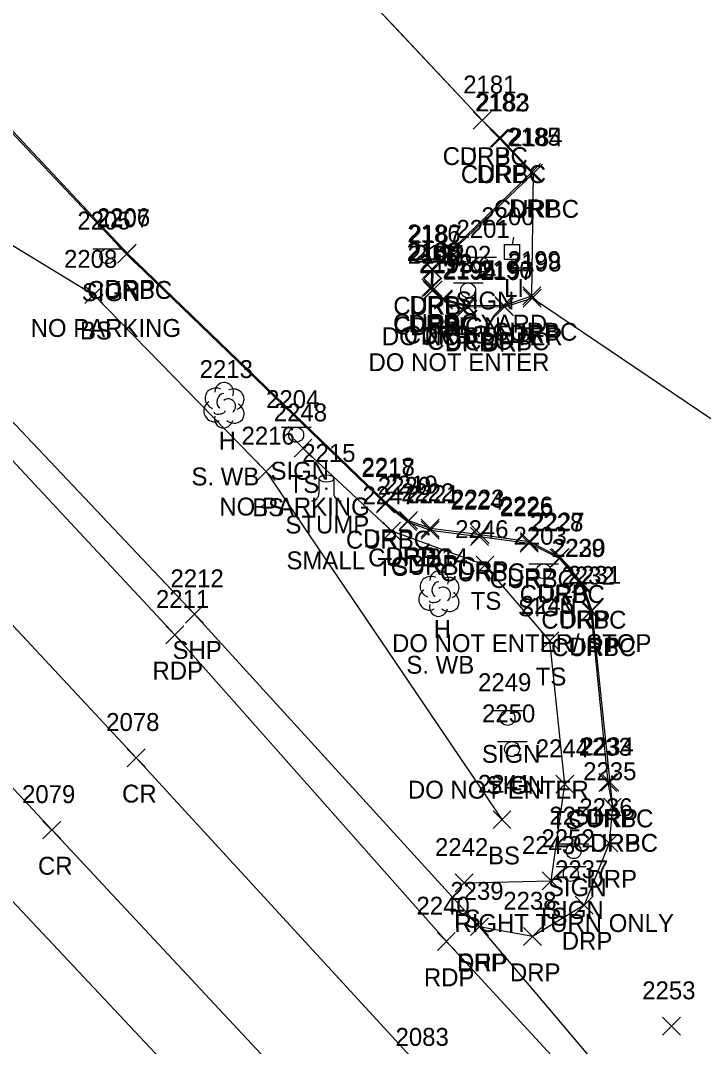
# Model space of a CAD drawing. Extents: x 1623612 to 1625808, y 621345 to 627748.
# Drawn here: x 1624292.6 to 1624368.9, y 626796.7 to 626911.4 of the extents above; entities that cross this region are included whole.
import ezdxf

# ---------------------------------------------------------------- set-up
doc = ezdxf.new("R2010")
doc.units = 0
for name, color, linetype in [('L_A', 7, 'Continuous'), ('L_C', 7, 'Continuous'), ('L_I', 7, 'Continuous'), ('L_TIC', 7, 'Continuous'), ('LELB', 7, 'Continuous'), ('LSOGP', 7, 'Continuous'), ('LTD', 7, 'Continuous'), ('LTS', 7, 'Continuous'), ('P_A', 7, 'Continuous'), ('P_I', 7, 'Continuous'), ('P_TIC', 7, 'Continuous'), ('PET', 7, 'Continuous'), ('PRC', 7, 'Continuous'), ('PSP', 7, 'Continuous'), ('R_A', 7, 'Continuous'), ('R_I', 7, 'Continuous'), ('R_TIC', 7, 'Continuous'), ('RC', 7, 'Continuous'), ('RDP', 7, 'Continuous'), ('S_A', 7, 'Continuous'), ('S_C', 7, 'Continuous'), ('S_I', 7, 'Continuous'), ('SSGN', 7, 'Continuous'), ('U_A', 7, 'Continuous'), ('U_C', 7, 'Continuous'), ('U_I', 7, 'Continuous'), ('ULP', 7, 'Continuous')]:
    doc.layers.add(name, color=color, linetype=linetype)

msp = doc.modelspace()

# ---------------------------------------------------------------- linework, layer by layer
at = {"layer": 'L_TIC'}
for points in [[(1624299.83, 626879.73), (1624301.83, 626881.73)], [(1624301.83, 626879.73), (1624299.83, 626881.73)], [(1624323.18, 626862.58), (1624325.18, 626864.58)], [(1624325.18, 626862.58), (1624323.18, 626864.58)], [(1624319.07, 626859.98), (1624321.07, 626861.98)], [(1624321.07, 626859.98), (1624319.07, 626861.98)], [(1624333.09, 626853.32), (1624335.09, 626855.32)], [(1624335.09, 626853.32), (1624333.09, 626855.32)], [(1624343.51, 626849.53), (1624345.51, 626851.53)], [(1624345.51, 626849.53), (1624343.51, 626851.53)], [(1624350.77, 626841.07), (1624352.77, 626843.07)], [(1624352.77, 626841.07), (1624350.77, 626843.07)], [(1624352.44, 626825.05), (1624354.44, 626827.05)], [(1624354.44, 626825.05), (1624352.44, 626827.05)], [(1624345.41, 626821.08), (1624347.41, 626823.08)], [(1624347.41, 626821.08), (1624345.41, 626823.08)], [(1624350.9, 626814.24), (1624352.9, 626816.24)], [(1624352.9, 626814.24), (1624350.9, 626816.24)], [(1624341.19, 626814.02), (1624343.19, 626816.02)], [(1624343.19, 626814.02), (1624341.19, 626816.02)], [(1624364.34, 626798.01), (1624366.34, 626800.01)], [(1624366.34, 626798.01), (1624364.34, 626800.01)]]:
    msp.add_lwpolyline(points, dxfattribs=at)
at = {"layer": 'LELB'}
for points in [[(1624269.61, 626899.7), (1624300.83, 626880.73), (1624320.07, 626860.98), (1624346.41, 626822.08)], [(1624342.19, 626815.02), (1624351.9, 626815.24), (1624353.44, 626826.05), (1624351.77, 626842.07), (1624344.51, 626850.53), (1624334.09, 626854.32), (1624324.18, 626863.58)]]:
    msp.add_lwpolyline(points, dxfattribs=at)
at = {"layer": 'LSOGP'}
msp.add_lwpolyline([(1624379.94, 626859.96), (1624349.79, 626880.33), (1624349.74, 626880.59), (1624349.93, 626894.32), (1624346.24, 626898.2), (1624344.21, 626900.21), (1624339.12, 626905.63), (1624334.03, 626911.05), (1624328.94, 626916.48)], dxfattribs=at)
at = {"layer": 'LTD'}
for p, q in [((1624315.33, 626868.42), (1624315.33, 626868.42)), ((1624315.33, 626868.42), (1624315.33, 626868.42)), ((1624339.34, 626847.38), (1624339.34, 626847.38)), ((1624339.34, 626847.38), (1624339.34, 626847.38))]:
    msp.add_line(p, q, dxfattribs=at)
for centre in [(1624315.38, 626869.86), (1624339.39, 626848.82)]:
    msp.add_arc(centre, 1.05, 335.5272, 180.9563, dxfattribs=at)
for centre, major_axis, ratio, start_param, end_param in [((1624314.54, 626869.09), (1.21, -0.51), 0.895232, 1.570796, 4.712389), ((1624316.37, 626869.01), (-1.14, -0.48), 0.949671, 1.570796, 4.712389), ((1624315.12, 626868.88), (-0.208, -0.792), 0.645439, 3.141593, 6.283185), ((1624315.83, 626868.26), (-0.5, 0.667), 0.989748, 3.141593, 6.283185), ((1624314.25, 626867.71), (0.58, -1.04), 0.959034, 3.141593, 6.283185), ((1624316.33, 626867.59), (-1.09, 0.79), 0.841452, 1.570796, 4.712389), ((1624315.33, 626866.92), (0.26, 1.06), 0.942809, 1.570796, 4.712389), ((1624314.87, 626867.67), (-0.625, -0.083), 0.423636, 0, 3.141593), ((1624338.55, 626848.05), (1.21, -0.51), 0.895232, 1.570796, 4.712389), ((1624339.14, 626847.84), (-0.208, -0.792), 0.645439, 3.141593, 6.283185), ((1624340.39, 626847.97), (-1.14, -0.48), 0.949671, 1.570796, 4.712389), ((1624338.26, 626846.67), (0.58, -1.04), 0.959034, 3.141593, 6.283185), ((1624339.84, 626847.22), (-0.5, 0.667), 0.989748, 3.141593, 6.283185), ((1624340.34, 626846.55), (-1.09, 0.79), 0.841452, 1.570796, 4.712389), ((1624339.34, 626845.88), (0.26, 1.06), 0.942809, 1.570796, 4.712389), ((1624338.89, 626846.63), (-0.625, -0.083), 0.423636, 0, 3.141593)]:
    msp.add_ellipse(centre, major_axis=major_axis, ratio=ratio, start_param=start_param, end_param=end_param, dxfattribs=at)
at = {"layer": 'LTS'}
for p, q in [((1624325.96, 626860.19), (1624325.96, 626858.52)), ((1624327.63, 626860.02), (1624327.63, 626860.19)), ((1624327.63, 626860.19), (1624327.63, 626858.52)), ((1624326.8, 626859.05), (1624326.8, 626859.05)), ((1624326.8, 626859.05), (1624326.8, 626859.05)), ((1624326.8, 626859.02), (1624326.8, 626859.02))]:
    msp.add_line(p, q, dxfattribs=at)
msp.add_circle((1624326.8, 626859.05), 0.0833, dxfattribs=at)
for centre, start, end in [((1624325.13, 626858.52), 270, 360), ((1624328.46, 626858.52), 180, 270)]:
    msp.add_arc(centre, 0.833, start, end, dxfattribs=at)
msp.add_ellipse((1624326.8, 626860.19), major_axis=(-0.833, 0), ratio=0.5, dxfattribs=at)
at = {"layer": 'P_TIC'}
for points in [[(1624311.07, 626844.04), (1624313.07, 626846.04)], [(1624313.07, 626844.04), (1624311.07, 626846.04)], [(1624308.88, 626841.73), (1624310.88, 626843.73)], [(1624310.88, 626841.73), (1624308.88, 626843.73)], [(1624304.54, 626827.99), (1624306.54, 626829.99)], [(1624306.54, 626827.99), (1624304.54, 626829.99)], [(1624295.14, 626819.93), (1624297.14, 626821.93)], [(1624297.14, 626819.93), (1624295.14, 626821.93)], [(1624342.91, 626809.12), (1624344.91, 626811.12)], [(1624344.91, 626809.12), (1624342.91, 626811.12)], [(1624339.2, 626807.47), (1624341.2, 626809.47)], [(1624341.2, 626807.47), (1624339.2, 626809.47)]]:
    msp.add_lwpolyline(points, dxfattribs=at)
at = {"layer": 'PET'}
msp.add_lwpolyline([(1624211.36, 626948.94), (1624238.72, 626919.55), (1624262.36, 626893.71), (1624286.05, 626868.28), (1624309.88, 626842.73), (1624340.2, 626808.47), (1624365.34, 626781.16), (1624395.18, 626750.47), (1624419.59, 626724.64), (1624445.91, 626697.02), (1624473.1, 626668.14), (1624507.26, 626632.06), (1624527.99, 626609.86), (1624550.6, 626585.36), (1624578.26, 626556.05), (1624603.3, 626530.62), (1624620.59, 626513.39), (1624649.07, 626495.66), (1624671.18, 626489.46), (1624702.74, 626490.16)], dxfattribs=at)
at = {"layer": 'PRC'}
for points in [[(1624202.38, 626941), (1624231.95, 626909.33), (1624268.3, 626868.91), (1624305.54, 626828.99), (1624337.86, 626793.81), (1624369.19, 626760.84), (1624403.29, 626724.16), (1624436.76, 626689.12), (1624471.08, 626653.03), (1624500.99, 626619.01), (1624533.46, 626585.06), (1624572.18, 626543.82), (1624598.35, 626515.6), (1624627.03, 626484.27), (1624657.97, 626450.75), (1624685.1, 626421.27), (1624710.89, 626393.93)], [(1624192.12, 626932.46), (1624222.52, 626900.06), (1624257.95, 626861.76), (1624296.14, 626820.93), (1624328.33, 626786.43), (1624360.02, 626752.63), (1624393.53, 626716.71), (1624427.43, 626680.74), (1624459.98, 626645.81), (1624494.27, 626609.22)], [(1624186.13, 626926.24), (1624216.09, 626894.04), (1624252.24, 626855.54), (1624289.91, 626814.88), (1624322.01, 626780.73), (1624353.66, 626746.64), (1624386.67, 626711.08), (1624421.34, 626674.27), (1624454.07, 626638.87), (1624487.99, 626602.6), (1624516.65, 626571.23)]]:
    msp.add_lwpolyline(points, dxfattribs=at)
at = {"layer": 'PSP'}
msp.add_lwpolyline([(1624213.53, 626951.11), (1624241.13, 626921.37), (1624264.77, 626895.8), (1624288.11, 626870.32), (1624312.07, 626845.04), (1624343.91, 626810.12), (1624367.27, 626782.46), (1624384.8, 626765.81), (1624396.96, 626752.53), (1624422.27, 626726.83), (1624449.32, 626699.43), (1624476.73, 626671.47), (1624511.72, 626635.98), (1624532.99, 626613.93), (1624555.81, 626591.77), (1624557.1, 626590.85), (1624584.71, 626562.13), (1624609.17, 626536.98), (1624624.05, 626517.59), (1624651.19, 626501.54), (1624672.81, 626495.1), (1624698.38, 626495.38)], dxfattribs=at)
at = {"layer": 'R_TIC'}
for points in [[(1624343.21, 626899.21), (1624345.21, 626901.21)], [(1624345.21, 626899.21), (1624343.21, 626901.21)], [(1624343.21, 626899.21), (1624345.21, 626901.21)], [(1624345.21, 626899.21), (1624343.21, 626901.21)], [(1624345.1, 626897.22), (1624347.1, 626899.22)], [(1624347.1, 626897.22), (1624345.1, 626899.22)], [(1624345.24, 626897.2), (1624347.24, 626899.2)], [(1624347.24, 626897.2), (1624345.24, 626899.2)], [(1624348.7, 626893.38), (1624350.7, 626895.38)], [(1624350.7, 626893.38), (1624348.7, 626895.38)], [(1624348.93, 626893.32), (1624350.93, 626895.32)], [(1624350.93, 626893.32), (1624348.93, 626895.32)], [(1624303.48, 626884.26), (1624305.48, 626886.26)], [(1624305.48, 626884.26), (1624303.48, 626886.26)], [(1624303.56, 626884.38), (1624305.56, 626886.38)], [(1624305.56, 626884.38), (1624303.56, 626886.38)], [(1624337.59, 626882.57), (1624339.59, 626884.57)], [(1624339.59, 626882.57), (1624337.59, 626884.57)], [(1624337.68, 626882.49), (1624339.68, 626884.49)], [(1624339.68, 626882.49), (1624337.68, 626884.49)], [(1624337.46, 626880.51), (1624339.46, 626882.51)], [(1624339.46, 626880.51), (1624337.46, 626882.51)], [(1624337.66, 626880.58), (1624339.66, 626882.58)], [(1624339.66, 626880.58), (1624337.66, 626882.58)], [(1624337.66, 626880.19), (1624339.66, 626882.19)], [(1624339.66, 626880.19), (1624337.66, 626882.19)], [(1624337.73, 626880.29), (1624339.73, 626882.29)], [(1624339.73, 626880.29), (1624337.73, 626882.29)], [(1624348.74, 626879.59), (1624350.74, 626881.59)], [(1624350.74, 626879.59), (1624348.74, 626881.59)], [(1624338.86, 626879.27), (1624340.86, 626881.27)], [(1624340.86, 626879.27), (1624338.86, 626881.27)], [(1624338.87, 626879.13), (1624340.87, 626881.13)], [(1624340.87, 626879.13), (1624338.87, 626881.13)], [(1624341.45, 626878.57), (1624343.45, 626880.57)], [(1624343.45, 626878.57), (1624341.45, 626880.57)], [(1624345.6, 626878.52), (1624347.6, 626880.52)], [(1624347.6, 626878.52), (1624345.6, 626880.52)], [(1624348.79, 626879.33), (1624350.79, 626881.33)], [(1624350.79, 626879.33), (1624348.79, 626881.33)], [(1624341.53, 626878.4), (1624343.53, 626880.4)], [(1624343.53, 626878.4), (1624341.53, 626880.4)], [(1624345.68, 626878.37), (1624347.68, 626880.37)], [(1624347.68, 626878.37), (1624345.68, 626880.37)], [(1624332.4, 626856.36), (1624334.4, 626858.36)], [(1624334.4, 626856.36), (1624332.4, 626858.36)], [(1624332.42, 626856.51), (1624334.42, 626858.51)], [(1624334.42, 626856.51), (1624332.42, 626858.51)], [(1624334.88, 626854.37), (1624336.88, 626856.37)], [(1624336.88, 626854.37), (1624334.88, 626856.37)], [(1624334.98, 626854.52), (1624336.98, 626856.52)], [(1624336.98, 626854.52), (1624334.98, 626856.52)], [(1624337.4, 626853.65), (1624339.4, 626855.65)], [(1624339.4, 626853.65), (1624337.4, 626855.65)], [(1624337.4, 626853.43), (1624339.4, 626855.43)], [(1624339.4, 626853.43), (1624337.4, 626855.43)], [(1624342.9, 626852.71), (1624344.9, 626854.71)], [(1624344.9, 626852.71), (1624342.9, 626854.71)], [(1624342.99, 626852.94), (1624344.99, 626854.94)], [(1624344.99, 626852.94), (1624342.99, 626854.94)], [(1624348.47, 626852.16), (1624350.47, 626854.16)], [(1624350.47, 626852.16), (1624348.47, 626854.16)], [(1624348.46, 626851.96), (1624350.46, 626853.96)], [(1624350.46, 626851.96), (1624348.46, 626853.96)], [(1624351.81, 626850.29), (1624353.81, 626852.29)], [(1624353.81, 626850.29), (1624351.81, 626852.29)], [(1624351.93, 626850.38), (1624353.93, 626852.38)], [(1624353.93, 626850.38), (1624351.93, 626852.38)], [(1624354.22, 626847.42), (1624356.22, 626849.42)], [(1624356.22, 626847.42), (1624354.22, 626849.42)], [(1624354.36, 626847.45), (1624356.36, 626849.45)], [(1624356.36, 626847.45), (1624354.36, 626849.45)], [(1624355.32, 626844.35), (1624357.32, 626846.35)], [(1624357.32, 626844.35), (1624355.32, 626846.35)], [(1624355.46, 626844.43), (1624357.46, 626846.43)], [(1624357.46, 626844.43), (1624355.46, 626846.43)], [(1624357.24, 626825.22), (1624359.24, 626827.22)], [(1624359.24, 626825.22), (1624357.24, 626827.22)], [(1624357.45, 626825.27), (1624359.45, 626827.27)], [(1624359.45, 626825.27), (1624357.45, 626827.27)], [(1624357.74, 626822.49), (1624359.74, 626824.49)], [(1624359.74, 626822.49), (1624357.74, 626824.49)], [(1624357.74, 626822.49), (1624359.74, 626824.49)], [(1624359.74, 626822.49), (1624357.74, 626824.49)], [(1624357.37, 626818.47), (1624359.37, 626820.47)], [(1624359.37, 626818.47), (1624357.37, 626820.47)], [(1624354.6, 626811.54), (1624356.6, 626813.54)], [(1624356.6, 626811.54), (1624354.6, 626813.54)], [(1624342.91, 626809.12), (1624344.91, 626811.12)], [(1624344.91, 626809.12), (1624342.91, 626811.12)], [(1624348.82, 626808.02), (1624350.82, 626810.02)], [(1624350.82, 626808.02), (1624348.82, 626810.02)]]:
    msp.add_lwpolyline(points, dxfattribs=at)
at = {"layer": 'RC'}
for points in [[(1624231.15, 626965.86), (1624258.61, 626934.06), (1624261.29, 626931.24), (1624262.15, 626930.41), (1624263.93, 626928.52), (1624264.52, 626927.67), (1624281.01, 626910.1), (1624304.48, 626885.26), (1624333.4, 626857.36), (1624335.88, 626855.37), (1624338.4, 626854.43), (1624343.9, 626853.71), (1624349.46, 626852.96), (1624352.81, 626851.29), (1624355.22, 626848.42), (1624356.32, 626845.35), (1624358.24, 626826.22), (1624358.74, 626823.49)], [(1624344.21, 626900.21), (1624346.24, 626898.2), (1624349.93, 626894.32), (1624338.68, 626883.49), (1624338.66, 626881.58), (1624338.73, 626881.29), (1624339.86, 626880.27), (1624342.45, 626879.57), (1624346.6, 626879.52), (1624349.74, 626880.59)]]:
    msp.add_lwpolyline(points, dxfattribs=at)
at = {"layer": 'RDP'}
for points in [[(1624231.31, 626965.81), (1624258.73, 626934.16), (1624261.42, 626931.35), (1624262.26, 626930.45), (1624264.08, 626928.6), (1624264.65, 626927.89), (1624281.2, 626910.24), (1624304.56, 626885.38), (1624333.42, 626857.51), (1624335.98, 626855.52), (1624338.4, 626854.65), (1624343.99, 626853.94), (1624349.47, 626853.16), (1624352.93, 626851.38), (1624355.36, 626848.45), (1624356.46, 626845.43), (1624358.45, 626826.27), (1624358.74, 626823.49), (1624358.37, 626819.47), (1624355.6, 626812.54), (1624349.82, 626809.02), (1624343.91, 626810.12)], [(1624272.58, 626959.35), (1624272.09, 626956.25), (1624272.59, 626952.78), (1624273.49, 626950.81), (1624274.85, 626950.01), (1624276.13, 626950.18), (1624287.41, 626960.78), (1624314.39, 626932.24), (1624320.57, 626925.44), (1624323.85, 626921.9), (1624344.21, 626900.21), (1624346.1, 626898.22), (1624349.7, 626894.38), (1624338.59, 626883.57), (1624338.46, 626881.51), (1624338.66, 626881.19), (1624339.87, 626880.13), (1624342.53, 626879.4), (1624346.68, 626879.37), (1624349.79, 626880.33)]]:
    msp.add_lwpolyline(points, dxfattribs=at)
at = {"layer": 'SSGN'}
for p, q in [((1624300.69, 626885.86), (1624304.02, 626885.86)), ((1624302.34, 626885.03), (1624302.34, 626885.03)), ((1624342.48, 626884.93), (1624345.81, 626884.93)), ((1624344.12, 626884.1), (1624344.12, 626884.1)), ((1624340.98, 626882.04), (1624344.31, 626882.04)), ((1624342.63, 626881.21), (1624342.63, 626881.21)), ((1624321.77, 626865.92), (1624325.1, 626865.92)), ((1624323.42, 626865.08), (1624323.42, 626865.08)), ((1624349.41, 626850.65), (1624352.74, 626850.65)), ((1624351.06, 626849.82), (1624351.06, 626849.82)), ((1624345.38, 626834.28), (1624348.72, 626834.28)), ((1624347.03, 626833.45), (1624347.03, 626833.45)), ((1624345.9, 626830.8), (1624349.23, 626830.8)), ((1624347.54, 626829.97), (1624347.54, 626829.97)), ((1624352.76, 626819.39), (1624356.1, 626819.39)), ((1624354.41, 626818.56), (1624354.41, 626818.56)), ((1624352.45, 626816.86), (1624355.78, 626816.86)), ((1624354.1, 626816.02), (1624354.1, 626816.02))]:
    msp.add_line(p, q, dxfattribs=at)
for centre in [(1624302.34, 626885.03), (1624344.12, 626884.1), (1624342.63, 626881.21), (1624323.42, 626865.08), (1624351.06, 626849.82), (1624347.03, 626833.45), (1624347.54, 626829.97), (1624354.41, 626818.56), (1624354.1, 626816.02)]:
    msp.add_circle(centre, 0.833, dxfattribs=at)
at = {"layer": 'ULP'}
for p, q in [((1624346.7, 626884.66), (1624346.7, 626886.33)), ((1624346.7, 626886.33), (1624348.37, 626886.33)), ((1624347.7, 626887.16), (1624347.54, 626886.33)), ((1624348.37, 626886.33), (1624348.37, 626884.66)), ((1624347.54, 626885.49), (1624347.54, 626885.49)), ((1624348.37, 626884.66), (1624346.7, 626884.66)), ((1624347.29, 626883.83), (1624347.54, 626884.66))]:
    msp.add_line(p, q, dxfattribs=at)

# ---------------------------------------------------------------- texts
at = {"layer": 'L_A'}
for s, p in [('BS', (1624299.27, 626875.73)), ('H', (1624314.77, 626863.42)), ('TS', (1624322.59, 626858.58)), ('BS', (1624318.51, 626855.98)), ('STUMP', (1624322.22, 626854.05)), ('TS', (1624332.5, 626849.32)), ('TS', (1624342.92, 626845.53)), ('H', (1624338.78, 626842.38)), ('TS', (1624350.18, 626837.07)), ('TS', (1624351.85, 626821.05)), ('BS', (1624344.85, 626817.08)), ('TS', (1624340.6, 626810.02)), ('TS', (1624350.31, 626810.24))]:
    msp.add_text(s, height=2, dxfattribs=at).set_placement(p)
at = {"layer": 'L_C'}
for s, p in [('S. WB', (1624311.72, 626859.42)), ('SMALL', (1624322.34, 626850.05)), ('S. WB', (1624335.73, 626838.38))]:
    msp.add_text(s, height=2, dxfattribs=at).set_placement(p)
at = {"layer": 'L_I'}
for s, p in [('2208', (1624297.49, 626883.73)), ('2213', (1624312.64, 626871.42)), ('2248', (1624320.92, 626866.58)), ('2216', (1624317.32, 626863.98)), ('2215', (1624324.1, 626862.05)), ('2247', (1624330.83, 626857.32)), ('2246', (1624341.19, 626853.53)), ('2214', (1624336.65, 626850.38)), ('2245', (1624348.51, 626845.07)), ('2244', (1624350.18, 626829.05)), ('2241', (1624343.72, 626825.08)), ('2242', (1624338.93, 626818.02)), ('2243', (1624348.64, 626818.24)), ('2253', (1624362.08, 626802.01))]:
    msp.add_text(s, height=2, dxfattribs=at).set_placement(p)
at = {"layer": 'P_A'}
for s, p in [('SHP', (1624309.61, 626840.04)), ('RDP', (1624307.37, 626837.73)), ('CR', (1624303.97, 626823.99)), ('CR', (1624294.58, 626815.93)), ('SHP', (1624341.45, 626805.12)), ('RDP', (1624337.69, 626803.47))]:
    msp.add_text(s, height=2, dxfattribs=at).set_placement(p)
at = {"layer": 'P_I'}
for s, p in [('2212', (1624309.38, 626848.04)), ('2211', (1624307.76, 626845.73)), ('2078', (1624302.2, 626831.99)), ('2079', (1624292.8, 626823.93)), ('2239', (1624340.64, 626813.12)), ('2240', (1624336.86, 626811.47)), ('2083', (1624334.52, 626796.81))]:
    msp.add_text(s, height=2, dxfattribs=at).set_placement(p)
at = {"layer": 'R_A'}
for s, p in [('CURBC', (1624339.79, 626895.21)), ('DRP', (1624341.7, 626895.21)), ('CURBC', (1624341.82, 626893.2)), ('DRP', (1624343.59, 626893.22)), ('CURBC', (1624345.51, 626889.32)), ('DRP', (1624347.19, 626889.38)), ('CURBC', (1624300.06, 626880.26)), ('DRP', (1624302.04, 626880.38)), ('CURBC', (1624334.27, 626878.49)), ('DRP', (1624336.08, 626878.57)), ('CURBC', (1624334.24, 626876.58)), ('CURBC', (1624334.31, 626876.29)), ('DRP', (1624335.95, 626876.51)), ('DRP', (1624336.14, 626876.19)), ('CURBC', (1624335.44, 626875.27)), ('DRP', (1624337.35, 626875.13)), ('CURBC', (1624345.32, 626875.59)), ('DRP', (1624347.28, 626875.33)), ('CURBC', (1624338.04, 626874.57)), ('DRP', (1624340.02, 626874.4)), ('CURBC', (1624342.18, 626874.52)), ('DRP', (1624344.17, 626874.37)), ('CURBC', (1624328.98, 626852.36)), ('DRP', (1624330.91, 626852.51)), ('CURBC', (1624331.46, 626850.37)), ('DRP', (1624333.47, 626850.52)), ('CURBC', (1624333.98, 626849.43)), ('DRP', (1624335.89, 626849.65)), ('CURBC', (1624339.48, 626848.71)), ('DRP', (1624341.48, 626848.94)), ('CURBC', (1624345.04, 626847.96)), ('DRP', (1624346.96, 626848.16)), ('DRP', (1624350.42, 626846.38)), ('CURBC', (1624348.39, 626846.29)), ('CURBC', (1624350.8, 626843.42)), ('DRP', (1624352.85, 626843.45)), ('CURBC', (1624351.9, 626840.35)), ('DRP', (1624353.95, 626840.43)), ('CURBC', (1624353.82, 626821.22)), ('DRP', (1624355.94, 626821.27)), ('CURBC', (1624354.33, 626818.49)), ('DRP', (1624356.23, 626818.49)), ('DRP', (1624355.85, 626814.47)), ('DRP', (1624353.09, 626807.54)), ('DRP', (1624341.4, 626805.12)), ('DRP', (1624347.3, 626804.02))]:
    msp.add_text(s, height=2, dxfattribs=at).set_placement(p)
at = {"layer": 'R_I'}
for s, p in [('2181', (1624342.08, 626903.21)), ('2181', (1624342.08, 626903.21)), ('2182', (1624343.4, 626901.22)), ('2183', (1624343.55, 626901.2)), ('2185', (1624347.01, 626897.38)), ('2184', (1624347.23, 626897.32)), ('2207', (1624301.14, 626888.26)), ('2206', (1624301.16, 626888.38)), ('2186', (1624335.84, 626886.57)), ('2187', (1624335.99, 626886.49)), ('2189', (1624335.76, 626884.51)), ('2190', (1624335.88, 626884.19)), ('2188', (1624335.96, 626884.58)), ('2191', (1624336.61, 626884.29)), ('2192', (1624337.16, 626883.27)), ('2193', (1624337.17, 626883.13)), ('2199', (1624347.04, 626883.59)), ('2198', (1624347.1, 626883.33)), ('2195', (1624339.76, 626882.57)), ('2194', (1624339.84, 626882.4)), ('2196', (1624343.85, 626882.52)), ('2197', (1624343.99, 626882.37)), ('2217', (1624330.71, 626860.36)), ('2218', (1624330.73, 626860.51)), ('2220', (1624332.54, 626858.37)), ('2219', (1624333.28, 626858.52)), ('2222', (1624335.14, 626857.65)), ('2221', (1624335.71, 626857.43)), ('2224', (1624340.64, 626856.71)), ('2223', (1624340.73, 626856.94)), ('2226', (1624346.16, 626856.16)), ('2225', (1624346.2, 626855.96)), ('2227', (1624349.67, 626854.38)), ('2228', (1624349.55, 626854.29)), ('2229', (1624351.95, 626851.42)), ('2230', (1624352.02, 626851.45)), ('2232', (1624353.06, 626848.35)), ('2231', (1624353.77, 626848.43)), ('2233', (1624354.98, 626829.22)), ('2234', (1624355.19, 626829.27)), ('2235', (1624355.48, 626826.49)), ('2235', (1624355.48, 626826.49)), ('2236', (1624355.05, 626822.47)), ('2237', (1624352.34, 626815.54)), ('2239', (1624340.64, 626813.12)), ('2238', (1624346.56, 626812.02))]:
    msp.add_text(s, height=2, dxfattribs=at).set_placement(p)
at = {"layer": 'S_A'}
for p in [(1624299.47, 626880.01), (1624341.26, 626879.08), (1624339.76, 626876.19), (1624320.56, 626860.06), (1624348.2, 626844.8), (1624344.17, 626828.43), (1624344.68, 626824.95), (1624351.55, 626813.53), (1624351.24, 626811)]:
    msp.add_text('SIGN', height=2, dxfattribs=at).set_placement(p)
at = {"layer": 'S_C'}
for s, p in [('NO PARKING', (1624293.76, 626876.01)), ('DO NOT ENTER', (1624332.99, 626875.08)), ('DO NOT ENTER', (1624331.5, 626872.19)), ('NO PARKING', (1624314.84, 626856.06)), ('DO NOT ENTER/ STOP', (1624334.13, 626840.8)), ('DO NOT ENTER', (1624335.9, 626824.43)), ('RIGHT TURN ONLY', (1624341.1, 626809.53))]:
    msp.add_text(s, height=2, dxfattribs=at).set_placement(p)
at = {"layer": 'S_I'}
for s, p in [('2205', (1624298.98, 626888.01)), ('2201', (1624341.33, 626887.08)), ('2202', (1624339.27, 626884.19)), ('2204', (1624320.06, 626868.06)), ('2203', (1624347.7, 626852.8)), ('2249', (1624343.74, 626836.43)), ('2250', (1624344.18, 626832.95)), ('2251', (1624351.7, 626821.53)), ('2252', (1624350.82, 626819))]:
    msp.add_text(s, height=2, dxfattribs=at).set_placement(p)
at = {"layer": 'U_A'}
msp.add_text('LI', height=2, dxfattribs=at).set_placement((1624346.64, 626880.49))
at = {"layer": 'U_C'}
msp.add_text('YARD', height=2, dxfattribs=at).set_placement((1624344.03, 626876.49))
at = {"layer": 'U_I'}
msp.add_text('2200', height=2, dxfattribs=at).set_placement((1624344.11, 626888.49))

doc.saveas('drawing.dxf')
